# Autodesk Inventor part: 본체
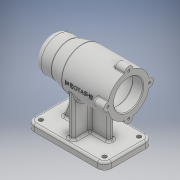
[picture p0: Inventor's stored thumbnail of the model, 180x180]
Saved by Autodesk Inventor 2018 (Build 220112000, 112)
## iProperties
Created: 2019-07
Part Number: 본체
Material: 일반
Document SubType Name: Modeling
Designer: USER
Density: 1 g/cm^3
Appearance: 기본값
Mass: 243.361 g
Surface Area: 663.658 cm^2
Volume: 243.361 cm^3
Author: USER
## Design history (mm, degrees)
sketch "스케치1"
  geometry: L1 (56, -35)-(-56, -35); L2 (-56, -35)-(-56, 35); L3 (-56, 35)-(56, 35); L4 (56, 35)-(56, -35); L5 (56, -35)-(-56, 35); L6 (-56, -35)-(56, 35); 1 further point
  constraints: 12 end point, 2 midpoint, 2 parallel, 1 horizontal, 1 perpendicular
  dimensions: "d0" = 112 distance of L2.end L3.end; "d1" = 70 distance of L1.end L2.end
extrude "돌출1" new body sketch "스케치1" distance "d2" = 10; taper "d3" = 0 deg
sketch "스케치2"
  geometry: L1 (56, 80)-(-56, 80); L2 (-56, 0)-(-56, 10) reference; L3 (56, 0)-(56, 10) reference; L4 (-56, 0)-(56, 0) reference; L5 (-56, 110)-(11, 110); L6 (11, 110)-(31, 105); L7 (31, 105)-(56, 105); L8 (56, 105)-(56, 80); L9 (-56, 80)-(-56, 110); 3 further points
  constraints: 12 end point, 2 midpoint, 2 vertical alignment, 1 horizontal, 1 parallel, 1 perpendicular, 1 vertical
  dimensions: "d4" = 80 distance between parallel lines of L4 L1; "d5" = 60 diameter of L5 L1; "d6" = 50 diameter of L7 L1; "d7" = 25 distance of L6.end L7.end; "d8" = 45 horizontal distance of L7.end L5.end
revolve "회전1" sketch "스케치2" stored, may be unused: angle "d9" = 90 deg
sketch "스케치3"
  geometry: L1 (56, 55)-(56, 105) reference; L2 (56, 80)-(-56, 80); L3 (-56, 50)-(-56, 110) reference; L4 (-56, 101)-(-41, 101); L5 (-41, 101)-(-41, 104); L6 (-41, 104)-(13, 104); L7 (13, 104)-(13, 101); L8 (13, 101)-(25, 101); L9 (25, 101)-(25, 97.5); L10 (25, 97.5)-(43, 97.5); L11 (43, 97.5)-(43, 96); L12 (43, 96)-(47, 96); L13 (47, 96)-(47, 90.5); L14 (47, 90.5)-(50, 90.5); L15 (50, 90.5)-(50, 80); 1 further point
  constraints: 26 end point, 10 perpendicular, 2 midpoint, 2 point on line, 1 horizontal, 1 vertical
  dimensions: "d10" = 42 diameter of L4 L2; "d11" = 48 diameter of L6 L2; "d12" = 42 diameter of L8 L2; "d13" = 54 distance of L5.end L6.end; "d14" = 15 distance of L4.start L4.end; "d15" = 12 distance of L7.end L8.end; "d16" = 18 distance of L9.end L10.end; "d17" = 35 diameter of L10 L2; "d18" = 32 diameter of L12 L2; "d19" = 4 distance of L11.end L12.end; "d20" = 3 distance of L13.end L14.end; "d21" = 21 diameter of L14 L2
revolve "회전2" sketch "스케치3" stored, may be unused: angle "d22" = 90 deg
sketch "스케치4"
  geometry: L1 (4, -28)-(-4, -28); L2 (-4, -28)-(-4, 28); L3 (-4, 28)-(4, 28); L4 (4, 28)-(4, -28); L5 (4, -28)-(-4, 28); L6 (-4, -28)-(4, 28); L7 (-56, 35)-(56, 35) reference; 1 further point
  constraints: 12 end point, 2 midpoint, 2 parallel, 1 horizontal, 1 perpendicular
  dimensions: "d23" = 8 distance of L2.end L3.end; "d25" = 7 distance between parallel lines of L7 L3
extrude "돌출2" join sketch "스케치4" stored distance "d26" = 10; taper "d27" = 0 deg
sketch "스케치5"
  geometry: L1 (-56, 10)-(56, 10) reference; L2 (36, 10)-(20.57, 52.393); L3 (11, 50)-(31, 55) reference; L4 (56, 0)-(56, 10) reference; 1 further point
  constraints: 2 end point, 2 point on line
  dimensions: "d28" = 110 deg angle of L1 L2; "d29" = 20 distance from line of L4 L2.start
feature "리브1" sketch "스케치5" dims "d30" = 1, "d31" = 8, "d32" = 0, "d33" = 0, "d34" = 1, "d35" = 1
sketch "스케치6"
  geometry: L1 (-56, 50)-(-4, 50) reference; L2 (-56, 0)-(-56, 10) reference; L3 (-56, 10)-(56, 10) reference; L4 (-31, 50)-(-31, 10); 1 further point
  constraints: 2 end point, 2 point on line, 1 perpendicular
  dimensions: "d37" = 25 distance between parallel lines of L2 L4
feature "리브2" sketch "스케치6" dims "d38" = 1, "d39" = 8, "d40" = 0, "d41" = 0, "d42" = 1, "d43" = 1
fillet "모깎기1" dims "d44" = 10
fillet "모깎기2" dims "d45" = 3
fillet "모깎기3" dims "d46" = 3
sketch "스케치7"
  geometry: A1 r 10 centre (-46, 25) between (-46, 35) and (-56, 25) reference; A2 r 10 centre (46, 25) between (56, 25) and (46, 35) reference; A3 r 10 centre (46, -25) between (46, -35) and (56, -25) reference; A4 r 10 centre (-46, -25) between (-56, -25) and (-46, -35) reference; 5 further points
  constraints: 4 coincident
hole "구멍1" sketch "스케치7" at (-46, 25), (46, 25), (46, -25), (-46, -25) diameter "d47" = 6; stored, may be unused: countersink angle "d51" = 90 deg, drill point angle "d53" = 118 deg; dims "d48" = 6, "d49" = 4, "d50" = 2, "d52" = 8
fillet "모깎기4" dims "d54" = 3
fillet "모깎기5" dims "d55" = 10
sketch "스케치8"
  geometry: C1 r 6 at (-30, 0); A1 r 30 centre (0, 0) between (29.314, -6.381) and (29.314, 6.381) reference; A2 r 30 centre (0, 0) between (29.314, 6.381) and (29.314, -6.381) reference; 1 further point
  constraints: 1 centre point, 1 horizontal alignment, 1 point on circle
  dimensions: "d56" = 12 diameter of C1
extrude "돌출3" join sketch "스케치8" distance "d57" = 16; taper "d58" = 0 deg
sketch "스케치9"
  geometry: A1 r 30 centre (30, 0) between (0.6, 5.97) and (0.6, -5.97) reference; A2 r 30 centre (30, 0) between (0.6, -5.97) and (24.03, -29.4) reference; A3 r 6 centre (0, 0) between (0.6, 5.97) and (0.6, -5.97) reference; 2 further points
  constraints: 1 coincident
hole "구멍2" sketch "스케치9" at (0, 0) diameter "d62" = 3.242; stored, may be unused: countersink angle "d66" = 90 deg, drill point angle "d68" = 118 deg; dims "d63" = 8, "d64" = 4, "d65" = 2, "d67" = 11
fillet "모깎기6" dims "d72" = 3
fillet "모깎기7" dims "d73" = 1
chamfer "모따기1" distance "d74" = 1; stored, may be unused: second distance "d75" = 2, angle "d76" = 45 deg
fillet "모깎기8" dims "d77" = 0.3
fillet "모깎기9" dims "d78" = 3
fillet "모깎기10" dims "d79" = 3
node "작업 평면4"
  node "작업 평면3"
sketch "스케치12"
  geometry: L1 (-33.5, 6.771)-(-33.5, 29.226) reference; L2 (-33.5, 22)-(-33.5, -22) reference; 3 further points
  constraints: 1 horizontal alignment, 1 midpoint, 1 other
  dimensions: "d81" = 42 distance from line of L1 point (8.5, 0)
feature "엠보싱1" sketch "스케치12" dims "d0" = 112, "d1" = 70, "d82" = 0.5, "d83" = 0
node "솔리드1"
pattern_circular "원형 패턴1" dims angle "d60" = 360 deg
pattern_circular "원형 패턴2" dims angle "d70" = 360 deg
